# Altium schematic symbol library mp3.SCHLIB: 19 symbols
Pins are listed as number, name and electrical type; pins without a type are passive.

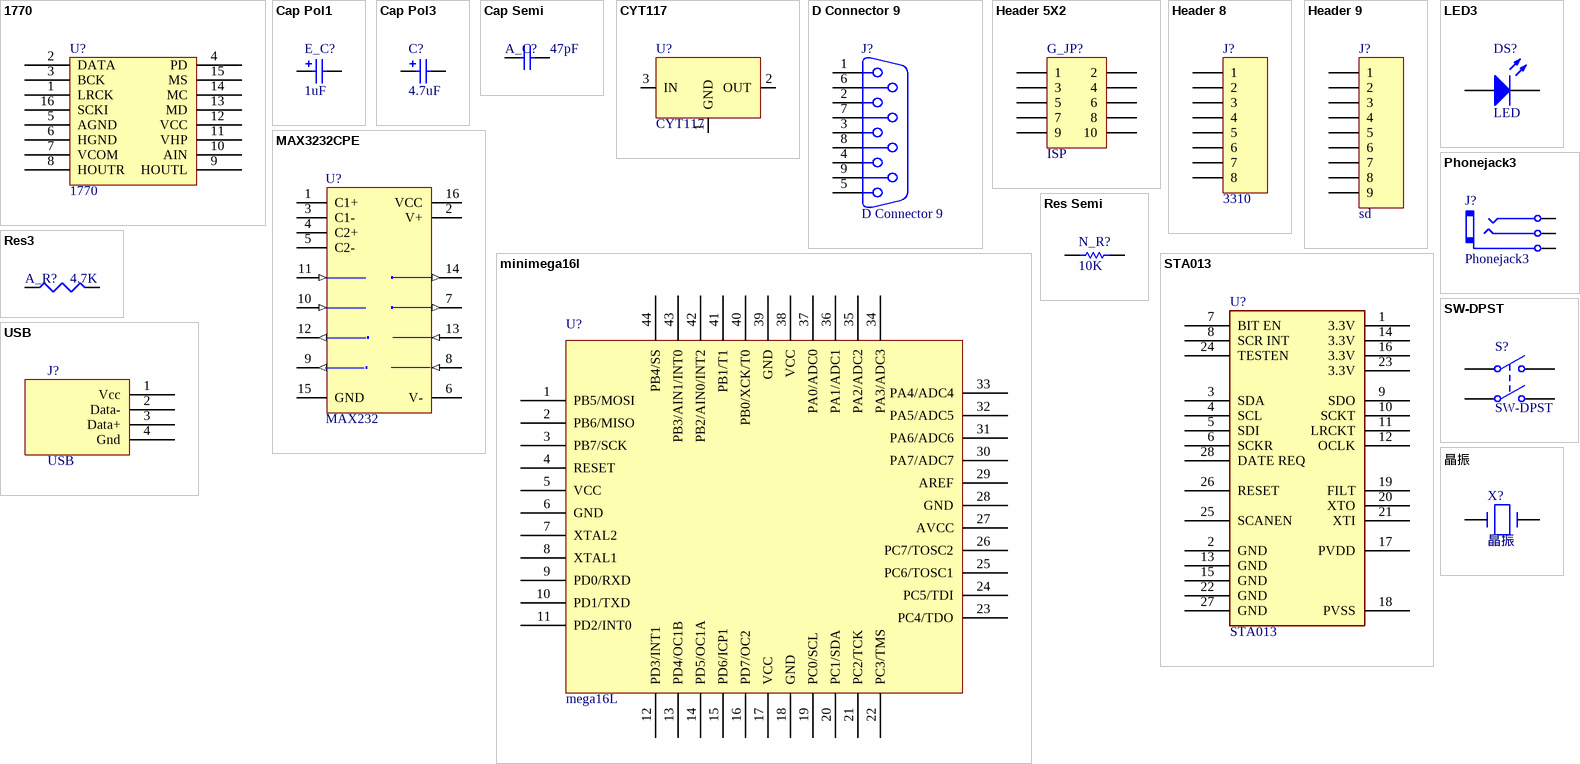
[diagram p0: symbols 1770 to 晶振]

## 1770
designator U?
footprint pcm1770
footprint pcm1770
pins: 1 LRCK, 2 DATA, 3 BCK, 4 PD, 5 AGND, 6 HGND, 7 VCOM, 8 HOUTR, 9 HOUTL, 10 AIN, 11 VHP, 12 VCC, 13 MD, 14 MC, 15 MS, 16 SCKI
2 alternate drawings of the same symbol

## Cap Pol1
designator E_C?  value 1uF
Polarized Capacitor (Radial); Manufacturer: Generic Components; Class: Passive
footprint 1206
pins: 1, 2
2 alternate drawings of the same symbol

## Cap Pol3
designator C?  value 4.7uF  (hidden comment: Cap Pol3)
Polarized Capacitor (Surface Mount)
footprint CC2012-0805
footprint CC4532-1812
footprint CC4564-1825
footprint CC5750-2220
footprint 1206
pins: 1, 2
2 alternate drawings of the same symbol

## Cap Semi
designator A_C?  value 47pF  (hidden comment: Cap Semi)
Capacitor (Semiconductor SIM Model)
footprint CC3216-1206
footprint CC1310-0504
footprint CC1608-0603
footprint CC1005-0402
footprint 0805
pins: 1, 2
2 alternate drawings of the same symbol

## CYT117
designator U?
footprint CYT117
pins: 1 GND, 2 OUT, 3 IN
2 alternate drawings of the same symbol

## D Connector 9
designator J?
Receptacle Assembly, 9 Position, Right Angle; Manufacturer: Generic Components; Positions: 9
footprint 232_9PIN
pins: 1, 2, 3, 4, 5, 6, 7, 8, 9
2 alternate drawings of the same symbol

## Header 5X2
designator G_JP?, comment ISP
Header, 5-Pin, Dual row
footprint ISP_2
pins: 1, 2, 3, 4, 5, 6, 7, 8, 9, 10
2 alternate drawings of the same symbol

## Header 8
designator J?, comment 3310
Header, 8-Pin
footprint HDR1X8
footprint nokia3310
footprint nokia3310
footprint nokia3310
pins: 1, 2, 3, 4, 5, 6, 7, 8
2 alternate drawings of the same symbol

## Header 9
designator J?, comment sd
Header, 9-Pin
footprint HDR1X9
footprint SD卡座
footprint SD卡座
footprint SD Card
pins: 1, 2, 3, 4, 5, 6, 7, 8, 9
2 alternate drawings of the same symbol

## LED3
designator DS?, comment LED
Typical BLUE SiC LED; Revision 1: Jul-2002: Re-released for DXP Platform.; Revision 2: 17-Dec-2003: PCB Footprint replaced.
footprint SMD _LED
footprint CC2012-0805
footprint 0805
pins: 1 A, 2 K
2 alternate drawings of the same symbol

## MAX3232CPE
designator U?, comment MAX232
3.0V TO 5.5V, Low-Power, up to 1Mbps, True RS-232 Transceiver Using Four 0.1µF External Capacitor; Package Information: Latest Revision: Aug-2000; Code - JEDEC: MS-001-BB
footprint NSO16
pins: 1 C1+, 2 V+ (power), 3 C1-, 4 C2+, 5 C2-, 6 V- (power), 7 T2OUT (out), 8 R2IN (in), 9 R2OUT (out), 10 T2IN (in), 11 T1IN (in), 12 R1OUT (out), 13 R1IN (in), 14 T1OUT (out), 15 GND (power), 16 VCC (power)
2 alternate drawings of the same symbol

## minimega16l
designator U?, comment mega16L
footprint 贴片Mega16L
pins: 1 PB5/MOSI, 2 PB6/MISO, 3 PB7/SCK, 4 RESET, 5 VCC, 6 GND, 7 XTAL2, 8 XTAL1, 9 PD0/RXD, 10 PD1/TXD, 11 PD2/INT0, 12 PD3/INT1, 13 PD4/OC1B, 14 PD5/OC1A, 15 PD6/ICP1, 16 PD7/OC2, 17 VCC, 18 GND, 19 PC0/SCL, 20 PC1/SDA, 21 PC2/TCK, 22 PC3/TMS, 23 PC4/TDO, 24 PC5/TDI, 25 PC6/TOSC1, 26 PC7/TOSC2, 27 AVCC, 28 GND, 29 AREF, 30 PA7/ADC7, 31 PA6/ADC6, 32 PA5/ADC5, 33 PA4/ADC4, 34 PA3/ADC3, 35 PA2/ADC2, 36 PA1/ADC1, 37 PA0/ADC0, 38 VCC, 39 GND, 40 PB0/XCK/T0, 41 PB1/T1, 42 PB2/AIN0/INT2, 43 PB3/AIN1/INT0, 44 PB4/SS
2 alternate drawings of the same symbol

## Phonejack3
designator J?
3-Conductor Jack
footprint 耳机插座3
footprint PCBComponent_1
footprint AXIAL-0.4
footprint 耳机插座3
pins: 1 A, 2 B, 3 C
2 alternate drawings of the same symbol

## Res3
designator A_R?  value 4.7K  (hidden comment: Res3)
Resistor
footprint C1608-0603
footprint CR3225-1210
footprint CR5025-2010
footprint CR6332-2512
footprint 0805
pins: 1, 2
2 alternate drawings of the same symbol

## Res Semi
designator N_R?  value 10K
Semiconductor Resistor; Manufacturer: Generic Components; Class: Passive
footprint 0805
pins: 1, 2
2 alternate drawings of the same symbol

## STA013
designator U?
footprint STA013
pins: 1 3.3V, 2 GND, 3 SDA, 4 SCL, 5 SDI, 6 SCKR, 7 BIT EN, 8 SCR INT, 9 SDO, 10 SCKT, 11 LRCKT, 12 OCLK, 13 GND, 14 3.3V (power), 15 GND, 16 3.3V, 17 PVDD, 18 PVSS, 19 FILT, 20 XTO, 21 XTI, 22 GND, 23 3.3V, 24 TESTEN, 25 SCANEN, 26 RESET, 27 GND, 28 DATE REQ
2 alternate drawings of the same symbol

## SW-DPST
designator S?
Double-Pole, Single-Throw Switch
footprint key_top
pins: 1 COMMON1, 2 NO1, 3 COMMON2, 4 NO2
2 alternate drawings of the same symbol

## USB
designator J?
footprint USB
pins: 1 Vcc, 2 Data-, 3 Data+, 4 Gnd
2 alternate drawings of the same symbol

## 晶振
designator X?
footprint SPST-2
footprint jinzhen
pins: 1, 2
2 alternate drawings of the same symbol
